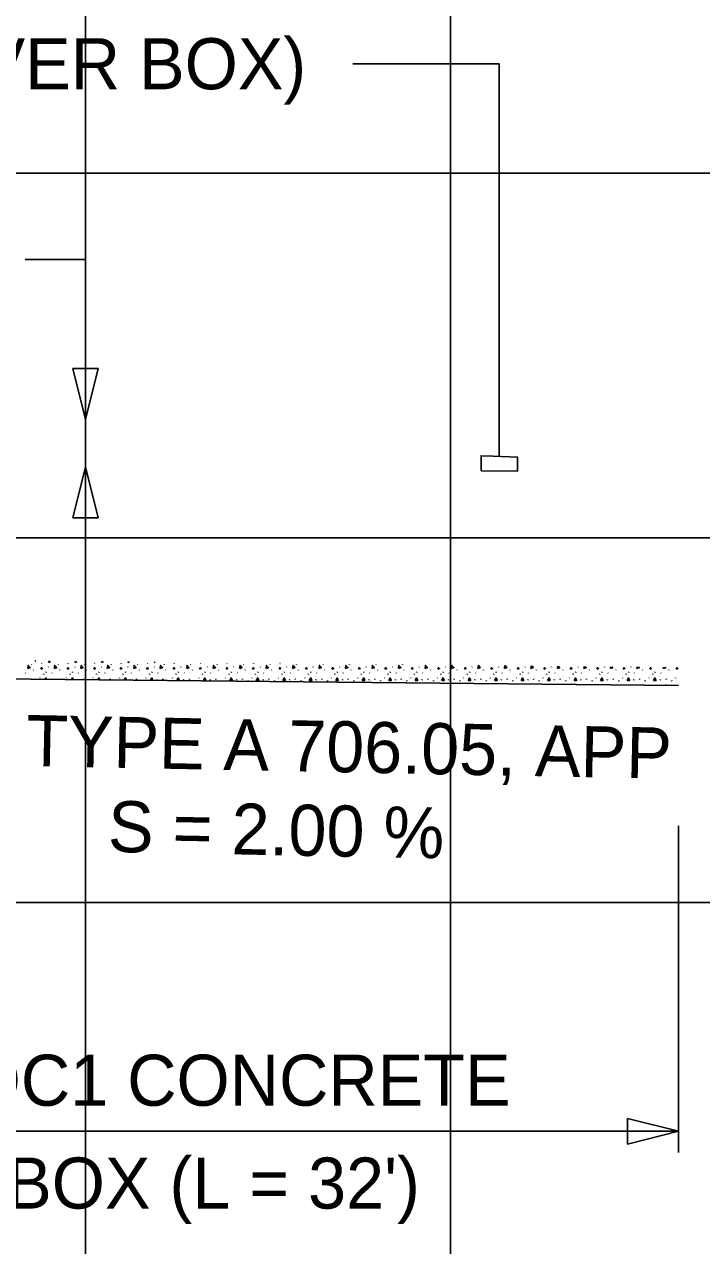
# Model space of a CAD drawing. Extents: x 0 to 340, y 0 to 220.
# Drawn here: x 120.83 to 139.38, y 33.09 to 66.57 of the extents above; entities that cross this region are included whole.
import ezdxf

# ---------------------------------------------------------------- set-up
doc = ezdxf.new("R2010")
doc.units = 0
for name, color, linetype in [('DR_P_Culvert', 7, 'Continuous'), ('MT_P_PCB', 7, 'Continuous'), ('MT_P_Work_Area', 7, 'Continuous'), ('PV_P_Shoulder', 7, 'Continuous'), ('SC_Scratch1', 7, 'Continuous')]:
    doc.layers.add(name, color=color, linetype=linetype)

msp = doc.modelspace()

# ---------------------------------------------------------------- linework, layer by layer
at = {"layer": 'DR_P_Culvert'}
msp.add_line((106.75, 48.766), (138.75, 48.446), dxfattribs=at)
at = {"layer": 'MT_P_PCB'}
for p, q in [((122.85, 57.14), (122.15, 57.14)), ((122.15, 57.14), (122.5, 55.74)), ((122.5, 57.14), (122.15, 57.14)), ((122.5, 55.74), (122.85, 57.14)), ((122.85, 57.14), (122.5, 57.14)), ((122.5, 57.14), (122.5, 55.74)), ((122.5, 55.74), (122.5, 57.14)), ((122.5, 54.442), (122.15, 53.042)), ((122.5, 53.042), (122.5, 54.442)), ((122.85, 53.042), (122.5, 54.442)), ((122.5, 54.442), (122.5, 53.042)), ((122.15, 53.042), (122.85, 53.042)), ((122.15, 53.042), (122.5, 53.042)), ((122.5, 53.042), (122.85, 53.042)), ((137.35, 36.577), (137.35, 35.877)), ((138.75, 36.227), (137.35, 36.577)), ((137.35, 36.577), (137.35, 36.227)), ((137.35, 36.227), (138.75, 36.227)), ((137.35, 35.877), (138.75, 36.227)), ((138.75, 36.227), (137.35, 36.227)), ((137.35, 36.227), (137.35, 35.877))]:
    msp.add_line(p, q, dxfattribs=at)
for points in [[(122.15, 57.14), (122.5, 55.74), (122.85, 57.14)], [(122.85, 53.042), (122.5, 54.442), (122.15, 53.042)], [(137.35, 35.877), (138.75, 36.227), (137.35, 36.577)]]:
    msp.add_lwpolyline(points, dxfattribs=at)
at = {"layer": 'MT_P_Work_Area'}
for p, q in [((133.838, 65.497), (129.823, 65.497)), ((133.838, 54.733), (133.838, 65.497)), ((120.85, 60.127), (122.5, 60.127)), ((122.5, 55.74), (122.5, 60.127)), ((133.338, 54.428), (133.338, 54.747)), ((133.338, 54.747), (133.338, 54.334)), ((134.338, 54.408), (134.338, 54.712)), ((134.338, 54.712), (134.338, 54.324)), ((122.5, 54.442), (122.5, 50.286)), ((138.75, 44.604), (138.75, 35.647)), ((106.75, 36.227), (138.75, 36.227))]:
    msp.add_line(p, q, dxfattribs=at)
msp.add_lwpolyline([(133.338, 54.334), (133.338, 54.747), (133.67, 54.74), (134.338, 54.712), (134.338, 54.324)], close=True, dxfattribs=at)
at = {"layer": 'PV_P_Shoulder'}
for p, q in [((122.5, 12.5), (122.5, 102.5)), ((132.5, 12.5), (132.5, 102.5)), ((22.5, 62.5), (222.5, 62.5)), ((22.5, 52.5), (222.5, 52.5)), ((22.5, 42.5), (222.5, 42.5))]:
    msp.add_line(p, q, dxfattribs=at)
at = {"layer": 'SC_Scratch1'}
for p, q in [((121.026, 49.026), (121.032, 49.017)), ((121.117, 49.116), (121.12, 49.122)), ((121.137, 49.122), (121.117, 49.116)), ((121.3, 49.048), (121.305, 49.062)), ((121.483, 48.95), (121.488, 48.964)), ((121.485, 49.082), (121.502, 49.118)), ((121.752, 49.026), (121.758, 49.017)), ((122.025, 49.048), (122.031, 49.062)), ((122.208, 48.95), (122.214, 48.964)), ((122.211, 49.082), (122.224, 49.111)), ((122.477, 49.026), (122.483, 49.017)), ((122.751, 49.048), (122.756, 49.062)), ((122.934, 48.95), (122.939, 48.964)), ((122.936, 49.082), (122.946, 49.104)), ((123.203, 49.026), (123.209, 49.017)), ((123.476, 49.048), (123.482, 49.062)), ((123.659, 48.95), (123.665, 48.964)), ((123.661, 49.082), (123.669, 49.097)), ((123.707, 49.096), (123.661, 49.082)), ((123.928, 49.026), (123.934, 49.017)), ((124.202, 49.048), (124.207, 49.062)), ((124.384, 48.95), (124.39, 48.964)), ((124.387, 49.082), (124.391, 49.09)), ((124.41, 49.089), (124.387, 49.082)), ((124.654, 49.026), (124.66, 49.017)), ((124.927, 49.048), (124.933, 49.062)), ((125.11, 48.95), (125.116, 48.964)), ((125.112, 49.082), (125.113, 49.082)), ((125.113, 49.082), (125.112, 49.082)), ((125.379, 49.026), (125.385, 49.017)), ((125.652, 49.048), (125.658, 49.062)), ((125.835, 48.95), (125.841, 48.964)), ((126.105, 49.026), (126.111, 49.017)), ((126.378, 49.048), (126.384, 49.062)), ((126.561, 48.95), (126.567, 48.964)), ((126.83, 49.026), (126.836, 49.017)), ((127.103, 49.048), (127.109, 49.062)), ((127.286, 48.95), (127.292, 48.964)), ((127.556, 49.026), (127.562, 49.017)), ((127.829, 49.048), (127.832, 49.055)), ((128.012, 48.95), (128.018, 48.964)), ((128.281, 49.026), (128.287, 49.017)), ((128.737, 48.95), (128.743, 48.964)), ((129.007, 49.026), (129.013, 49.017)), ((129.463, 48.95), (129.469, 48.964)), ((129.732, 49.026), (129.738, 49.017)), ((130.188, 48.95), (130.194, 48.964)), ((130.458, 49.026), (130.464, 49.017)), ((130.914, 48.95), (130.92, 48.964)), ((131.186, 49.022), (131.189, 49.017)), ((131.639, 48.95), (131.645, 48.964)), ((132.365, 48.95), (132.371, 48.964)), ((133.09, 48.95), (133.096, 48.964)), ((133.816, 48.95), (133.822, 48.964)), ((133.98, 48.914), (133.991, 48.994)), ((134.541, 48.95), (134.547, 48.964)), ((134.706, 48.914), (134.716, 48.986)), ((135.267, 48.95), (135.273, 48.964)), ((135.431, 48.914), (135.44, 48.979)), ((135.992, 48.95), (135.998, 48.964)), ((136.157, 48.914), (136.165, 48.972)), ((136.718, 48.95), (136.724, 48.964)), ((136.882, 48.914), (136.889, 48.965)), ((137.443, 48.95), (137.447, 48.959)), ((137.608, 48.914), (137.613, 48.957)), ((138.169, 48.95), (138.169, 48.952)), ((138.333, 48.914), (138.338, 48.95)), ((120.853, 48.795), (120.859, 48.786)), ((120.995, 48.628), (120.996, 48.623)), ((121.07, 48.868), (121.076, 48.881)), ((121.254, 48.648), (121.26, 48.662)), ((121.35, 48.753), (121.356, 48.766)), ((121.418, 48.809), (121.424, 48.822)), ((121.578, 48.795), (121.584, 48.786)), ((121.721, 48.628), (121.722, 48.616)), ((121.796, 48.868), (121.802, 48.881)), ((121.979, 48.648), (121.985, 48.662)), ((122.076, 48.753), (122.082, 48.766)), ((122.143, 48.809), (122.149, 48.822)), ((122.293, 48.61), (122.293, 48.611)), ((122.304, 48.795), (122.31, 48.786)), ((122.446, 48.628), (122.448, 48.615)), ((122.521, 48.868), (122.527, 48.881)), ((122.705, 48.648), (122.711, 48.662)), ((122.801, 48.753), (122.807, 48.766)), ((122.869, 48.809), (122.875, 48.822)), ((123.015, 48.603), (123.019, 48.611)), ((123.029, 48.795), (123.035, 48.786)), ((123.172, 48.628), (123.173, 48.615)), ((123.247, 48.868), (123.253, 48.881)), ((123.43, 48.648), (123.436, 48.662)), ((123.527, 48.753), (123.533, 48.766)), ((123.594, 48.809), (123.6, 48.822)), ((123.738, 48.597), (123.744, 48.611)), ((123.755, 48.795), (123.761, 48.786)), ((123.897, 48.628), (123.899, 48.615)), ((123.972, 48.868), (123.978, 48.881)), ((124.156, 48.648), (124.162, 48.662)), ((124.252, 48.753), (124.258, 48.766)), ((124.32, 48.809), (124.326, 48.822)), ((124.464, 48.597), (124.47, 48.611)), ((124.48, 48.795), (124.486, 48.786)), ((124.623, 48.628), (124.624, 48.615)), ((124.698, 48.868), (124.704, 48.881)), ((124.881, 48.648), (124.887, 48.662)), ((124.978, 48.753), (124.984, 48.766)), ((125.045, 48.809), (125.051, 48.822)), ((125.189, 48.597), (125.195, 48.611)), ((125.206, 48.795), (125.212, 48.786)), ((125.348, 48.628), (125.35, 48.615)), ((125.423, 48.868), (125.429, 48.881)), ((125.504, 48.582), (125.504, 48.578)), ((125.607, 48.648), (125.613, 48.662)), ((125.703, 48.753), (125.709, 48.766)), ((125.771, 48.809), (125.777, 48.822)), ((125.915, 48.597), (125.921, 48.611)), ((125.931, 48.795), (125.937, 48.786)), ((126.074, 48.628), (126.075, 48.615)), ((126.149, 48.868), (126.155, 48.881)), ((126.229, 48.582), (126.23, 48.571)), ((126.332, 48.648), (126.338, 48.662)), ((126.429, 48.753), (126.435, 48.766)), ((126.496, 48.809), (126.502, 48.822)), ((126.64, 48.597), (126.646, 48.611)), ((126.657, 48.795), (126.663, 48.786)), ((126.799, 48.628), (126.801, 48.615)), ((126.874, 48.868), (126.88, 48.881)), ((126.955, 48.582), (126.956, 48.569)), ((127.058, 48.648), (127.064, 48.662)), ((127.154, 48.753), (127.16, 48.766)), ((127.222, 48.809), (127.228, 48.822)), ((127.366, 48.597), (127.372, 48.611)), ((127.382, 48.795), (127.388, 48.786)), ((127.525, 48.628), (127.526, 48.615)), ((127.6, 48.868), (127.606, 48.881)), ((127.68, 48.582), (127.682, 48.569)), ((127.783, 48.648), (127.789, 48.662)), ((127.88, 48.753), (127.886, 48.766)), ((127.947, 48.809), (127.953, 48.822)), ((128.091, 48.597), (128.097, 48.611)), ((128.108, 48.795), (128.114, 48.786)), ((128.25, 48.628), (128.252, 48.615)), ((128.325, 48.868), (128.331, 48.881)), ((128.406, 48.582), (128.407, 48.569)), ((128.509, 48.648), (128.515, 48.662)), ((128.605, 48.753), (128.611, 48.766)), ((128.673, 48.809), (128.678, 48.822)), ((128.817, 48.597), (128.823, 48.611)), ((128.833, 48.795), (128.839, 48.786)), ((128.976, 48.628), (128.977, 48.615)), ((129.051, 48.868), (129.057, 48.881)), ((129.131, 48.582), (129.133, 48.569)), ((129.234, 48.648), (129.24, 48.662)), ((129.331, 48.753), (129.337, 48.766)), ((129.398, 48.809), (129.404, 48.822)), ((129.542, 48.597), (129.548, 48.611)), ((129.559, 48.795), (129.565, 48.786)), ((129.701, 48.628), (129.703, 48.615)), ((129.776, 48.868), (129.782, 48.881)), ((129.857, 48.582), (129.858, 48.569)), ((129.96, 48.648), (129.966, 48.662)), ((130.056, 48.753), (130.062, 48.766)), ((130.124, 48.809), (130.129, 48.822)), ((130.268, 48.597), (130.274, 48.611)), ((130.284, 48.795), (130.29, 48.786)), ((130.427, 48.628), (130.428, 48.615)), ((130.502, 48.868), (130.508, 48.881)), ((130.582, 48.582), (130.584, 48.569)), ((130.685, 48.648), (130.691, 48.662)), ((130.782, 48.753), (130.788, 48.766)), ((130.849, 48.809), (130.855, 48.822)), ((130.993, 48.597), (130.999, 48.611)), ((131.01, 48.795), (131.016, 48.786)), ((131.152, 48.628), (131.154, 48.615)), ((131.227, 48.868), (131.233, 48.881)), ((131.308, 48.582), (131.309, 48.569)), ((131.411, 48.648), (131.416, 48.662)), ((131.507, 48.753), (131.513, 48.766)), ((131.574, 48.809), (131.58, 48.822)), ((131.719, 48.597), (131.725, 48.611)), ((131.735, 48.795), (131.741, 48.786)), ((131.878, 48.628), (131.879, 48.615)), ((131.953, 48.868), (131.959, 48.881)), ((132.033, 48.582), (132.035, 48.569)), ((132.136, 48.648), (132.142, 48.662)), ((132.233, 48.753), (132.239, 48.766)), ((132.3, 48.809), (132.306, 48.822)), ((132.444, 48.597), (132.45, 48.611)), ((132.461, 48.795), (132.467, 48.786)), ((132.603, 48.628), (132.605, 48.615)), ((132.678, 48.868), (132.684, 48.881)), ((132.759, 48.582), (132.76, 48.569)), ((132.862, 48.648), (132.867, 48.662)), ((132.958, 48.753), (132.964, 48.766)), ((133.025, 48.809), (133.031, 48.822)), ((133.17, 48.597), (133.176, 48.611)), ((133.186, 48.795), (133.192, 48.786)), ((133.329, 48.628), (133.33, 48.615)), ((133.404, 48.868), (133.41, 48.881)), ((133.484, 48.582), (133.485, 48.569)), ((133.587, 48.648), (133.593, 48.662)), ((133.684, 48.753), (133.689, 48.766)), ((133.751, 48.809), (133.757, 48.822)), ((133.895, 48.597), (133.901, 48.611)), ((133.912, 48.795), (133.918, 48.786)), ((134.054, 48.628), (134.056, 48.615)), ((134.129, 48.868), (134.135, 48.881)), ((134.209, 48.582), (134.211, 48.569)), ((134.312, 48.648), (134.318, 48.662)), ((134.409, 48.753), (134.415, 48.766)), ((134.476, 48.809), (134.482, 48.822)), ((134.621, 48.597), (134.626, 48.611)), ((134.637, 48.795), (134.643, 48.786)), ((134.78, 48.628), (134.781, 48.615)), ((134.855, 48.868), (134.861, 48.881)), ((134.935, 48.582), (134.936, 48.569)), ((135.038, 48.648), (135.044, 48.662)), ((135.135, 48.753), (135.14, 48.766)), ((135.202, 48.809), (135.208, 48.822)), ((135.346, 48.597), (135.352, 48.611)), ((135.363, 48.795), (135.369, 48.786)), ((135.505, 48.628), (135.507, 48.615)), ((135.58, 48.868), (135.586, 48.881)), ((135.66, 48.582), (135.662, 48.569)), ((135.763, 48.648), (135.769, 48.662)), ((135.86, 48.753), (135.866, 48.766)), ((135.927, 48.809), (135.933, 48.822)), ((136.072, 48.597), (136.077, 48.611)), ((136.088, 48.795), (136.094, 48.786)), ((136.231, 48.628), (136.232, 48.615)), ((136.306, 48.868), (136.312, 48.881)), ((136.386, 48.582), (136.387, 48.569)), ((136.489, 48.648), (136.495, 48.662)), ((136.586, 48.753), (136.591, 48.766)), ((136.653, 48.809), (136.659, 48.822)), ((136.797, 48.597), (136.803, 48.611)), ((136.814, 48.795), (136.82, 48.786)), ((136.956, 48.628), (136.957, 48.615)), ((137.031, 48.868), (137.037, 48.881)), ((137.111, 48.582), (137.113, 48.569)), ((137.214, 48.648), (137.22, 48.662)), ((137.311, 48.753), (137.317, 48.766)), ((137.378, 48.809), (137.384, 48.822)), ((137.522, 48.597), (137.528, 48.611)), ((137.539, 48.795), (137.545, 48.786)), ((137.681, 48.628), (137.683, 48.615)), ((137.757, 48.868), (137.763, 48.881)), ((137.837, 48.582), (137.838, 48.569)), ((137.94, 48.648), (137.946, 48.662)), ((138.036, 48.753), (138.042, 48.766)), ((138.104, 48.809), (138.11, 48.822)), ((138.248, 48.597), (138.254, 48.611)), ((138.265, 48.795), (138.271, 48.786)), ((138.407, 48.628), (138.408, 48.615)), ((138.482, 48.868), (138.488, 48.881)), ((138.562, 48.582), (138.564, 48.569)), ((138.665, 48.648), (138.671, 48.662)), ((136.218, 48.474), (136.22, 48.471)), ((136.632, 48.47), (136.632, 48.467)), ((136.943, 48.474), (136.949, 48.465)), ((137.357, 48.47), (137.358, 48.46)), ((137.669, 48.474), (137.675, 48.465)), ((138.083, 48.47), (138.084, 48.457)), ((138.394, 48.474), (138.4, 48.465))]:
    msp.add_line(p, q, dxfattribs=at)
for points in [[(120.921, 48.914), (120.933, 48.999), (120.986, 48.944), (120.923, 48.915)], [(121.275, 48.898), (121.293, 48.935), (121.322, 48.913), (121.275, 48.898)], [(121.504, 49.118), (121.532, 49.097), (121.485, 49.082)], [(121.647, 48.914), (121.659, 48.999), (121.712, 48.944), (121.648, 48.915)], [(122, 48.898), (122.018, 48.935), (122.048, 48.913), (122, 48.898)], [(122.239, 49.111), (122.258, 49.097), (122.211, 49.082)], [(122.372, 48.914), (122.384, 48.999), (122.437, 48.944), (122.374, 48.915)], [(122.726, 48.898), (122.744, 48.935), (122.773, 48.913), (122.726, 48.898)], [(122.974, 49.104), (122.983, 49.097), (122.936, 49.082)], [(123.098, 48.914), (123.11, 48.999), (123.163, 48.944), (123.099, 48.915)], [(123.451, 48.898), (123.469, 48.935), (123.499, 48.913), (123.451, 48.898)], [(123.823, 48.914), (123.835, 48.999), (123.888, 48.944), (123.825, 48.915)], [(124.177, 48.898), (124.195, 48.935), (124.224, 48.913), (124.177, 48.898)], [(124.549, 48.914), (124.561, 48.999), (124.614, 48.944), (124.55, 48.915)], [(124.902, 48.898), (124.92, 48.935), (124.95, 48.913), (124.902, 48.898)], [(125.274, 48.914), (125.286, 48.999), (125.339, 48.944), (125.276, 48.915)], [(125.628, 48.898), (125.646, 48.935), (125.675, 48.913), (125.628, 48.898)], [(126, 48.914), (126.011, 48.999), (126.064, 48.944), (126.001, 48.915)], [(126.353, 48.898), (126.371, 48.935), (126.401, 48.913), (126.353, 48.898)], [(126.725, 48.914), (126.737, 48.999), (126.79, 48.944), (126.727, 48.915)], [(127.079, 48.898), (127.097, 48.935), (127.126, 48.913), (127.079, 48.898)], [(127.451, 48.914), (127.462, 48.999), (127.515, 48.944), (127.452, 48.915)], [(127.804, 48.898), (127.822, 48.935), (127.852, 48.913), (127.804, 48.898)], [(128.176, 48.914), (128.188, 48.999), (128.241, 48.944), (128.178, 48.915)], [(128.53, 48.898), (128.548, 48.935), (128.577, 48.913), (128.53, 48.898)], [(128.902, 48.914), (128.913, 48.999), (128.966, 48.944), (128.903, 48.915)], [(129.255, 48.898), (129.273, 48.935), (129.303, 48.913), (129.255, 48.898)], [(129.627, 48.914), (129.639, 48.999), (129.692, 48.944), (129.629, 48.915)], [(129.981, 48.898), (129.999, 48.935), (130.028, 48.913), (129.981, 48.898)], [(130.353, 48.914), (130.364, 48.999), (130.417, 48.944), (130.354, 48.915)], [(130.706, 48.898), (130.724, 48.935), (130.754, 48.913), (130.706, 48.898)], [(131.078, 48.914), (131.09, 48.999), (131.143, 48.944), (131.08, 48.915)], [(131.432, 48.898), (131.45, 48.935), (131.479, 48.913), (131.432, 48.898)], [(131.804, 48.914), (131.815, 48.999), (131.868, 48.944), (131.805, 48.915)], [(132.157, 48.898), (132.175, 48.935), (132.205, 48.913), (132.157, 48.898)], [(132.529, 48.914), (132.541, 48.999), (132.594, 48.944), (132.531, 48.915)], [(132.883, 48.898), (132.901, 48.935), (132.93, 48.913), (132.883, 48.898)], [(133.255, 48.914), (133.266, 48.999), (133.319, 48.944), (133.256, 48.915)], [(133.608, 48.898), (133.626, 48.935), (133.656, 48.913), (133.608, 48.898)], [(133.997, 48.993), (134.045, 48.944), (133.981, 48.915)], [(134.334, 48.898), (134.351, 48.935), (134.381, 48.913), (134.334, 48.898)], [(134.73, 48.986), (134.77, 48.944), (134.707, 48.915)], [(135.059, 48.898), (135.077, 48.935), (135.107, 48.913), (135.059, 48.898)], [(135.462, 48.979), (135.496, 48.944), (135.432, 48.915)], [(135.785, 48.898), (135.802, 48.935), (135.832, 48.913), (135.785, 48.898)], [(136.195, 48.971), (136.221, 48.944), (136.158, 48.915)], [(136.51, 48.898), (136.528, 48.935), (136.558, 48.913), (136.51, 48.898)], [(136.927, 48.964), (136.947, 48.944), (136.883, 48.915)], [(137.236, 48.898), (137.253, 48.935), (137.283, 48.913), (137.236, 48.898)], [(137.66, 48.957), (137.672, 48.944), (137.609, 48.915)], [(137.961, 48.898), (137.979, 48.935), (138.009, 48.913), (137.961, 48.898)], [(138.393, 48.95), (138.398, 48.944), (138.334, 48.915)], [(138.687, 48.898), (138.704, 48.935), (138.734, 48.913), (138.687, 48.898)], [(121.397, 48.619), (121.418, 48.659), (121.436, 48.619)], [(122.119, 48.612), (122.143, 48.659), (122.165, 48.612)], [(122.84, 48.605), (122.869, 48.659), (122.893, 48.604)], [(123.562, 48.598), (123.594, 48.659), (123.622, 48.597)], [(124.284, 48.591), (124.32, 48.659), (124.351, 48.59)], [(125.005, 48.583), (125.045, 48.659), (125.077, 48.589), (125.007, 48.583)], [(125.731, 48.583), (125.771, 48.659), (125.802, 48.589), (125.732, 48.583)], [(126.456, 48.583), (126.496, 48.659), (126.527, 48.589), (126.458, 48.583)], [(127.182, 48.583), (127.222, 48.659), (127.253, 48.589), (127.183, 48.583)], [(127.907, 48.583), (127.947, 48.659), (127.978, 48.589), (127.909, 48.583)], [(128.633, 48.583), (128.673, 48.659), (128.704, 48.589), (128.634, 48.583)], [(129.358, 48.583), (129.398, 48.659), (129.429, 48.589), (129.36, 48.583)], [(130.084, 48.583), (130.124, 48.659), (130.155, 48.589), (130.085, 48.583)], [(130.809, 48.583), (130.849, 48.659), (130.88, 48.589), (130.811, 48.583)], [(131.535, 48.583), (131.575, 48.659), (131.606, 48.589), (131.536, 48.583)], [(132.26, 48.583), (132.3, 48.659), (132.331, 48.589), (132.262, 48.583)], [(132.986, 48.583), (133.026, 48.659), (133.057, 48.589), (132.987, 48.583)], [(133.711, 48.583), (133.751, 48.659), (133.782, 48.589), (133.713, 48.583)], [(134.437, 48.583), (134.477, 48.659), (134.508, 48.589), (134.438, 48.583)], [(135.162, 48.583), (135.202, 48.659), (135.233, 48.589), (135.164, 48.583)], [(135.888, 48.583), (135.928, 48.659), (135.959, 48.589), (135.889, 48.583)], [(136.613, 48.583), (136.653, 48.659), (136.684, 48.589), (136.615, 48.583)], [(137.339, 48.583), (137.379, 48.659), (137.41, 48.589), (137.34, 48.583)], [(138.064, 48.583), (138.104, 48.659), (138.135, 48.589), (138.066, 48.583)], [(138.544, 48.448), (138.546, 48.454), (138.554, 48.448)]]:
    msp.add_lwpolyline(points, dxfattribs=at)

# ---------------------------------------------------------------- texts
at = {"layer": 'MT_P_Work_Area'}
for s, p in [('(OVER BOX)', (117.521, 64.797)), ('6" CLASS QC1 CONCRETE', (110.389, 36.927)), ("UNDER BOX (L = 32')", (113.152, 34.108))]:
    msp.add_text(s, height=1.4, dxfattribs=at).set_placement(p)
for s, p in [("8' X 4' CONDUIT, TYPE A 706.05, APP", (105.694, 46.547)), ('L = 40 FT     S = 2.00 %', (112.445, 44.102))]:
    msp.add_text(s, height=1.4, rotation=358.8542, dxfattribs=at).set_placement(p)

doc.saveas('drawing.dxf')
